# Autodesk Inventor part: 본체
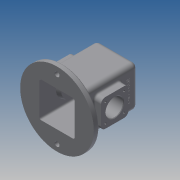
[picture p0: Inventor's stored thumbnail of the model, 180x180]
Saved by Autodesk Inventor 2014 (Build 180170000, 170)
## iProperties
Created: 2021-08
Part Number: 본체
Material: Generic
Document SubType Name: Modeling
Designer: kb542
Density: 1 g/cm^3
Appearance: Default
Author: kb542
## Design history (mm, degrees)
sketch "스케치1"
  geometry: L1 (37, 37)-(-37, 37); L2 (-37, 37)-(-37, -37); L3 (-37, -37)-(37, -37); L4 (37, -37)-(37, 37); L5 (37, 37)-(-37, -37); L6 (-37, 37)-(37, -37); 1 further point
  constraints: 12 end point, 2 midpoint, 2 parallel, 1 horizontal, 1 perpendicular
  dimensions: "d1" = 74 distance of L2.end L3.end; "d2" = 74 distance of L1.end L2.end
extrude "돌출1" new body sketch "스케치1" distance "d3" = 100; taper "d4" = 0 deg
feature "쉘1" dims "d5" = 5
sketch "스케치2"
  geometry: L1 (-32, -32)-(-32, 32) reference; L2 (-32, 32)-(32, 32) reference; L3 (32, 32)-(32, -32) reference; L4 (32, -32)-(-32, -32) reference; C1 r 67 at (0, 0); 1 further point
  constraints: 1 centre point, 1 coincident
  dimensions: "d6" = 134 diameter of C1
extrude "돌출2" join sketch "스케치2" distance "d7" = 10; taper "d8" = 0 deg
node "작업 평면1"
sketch "스케치3"
  geometry: C1 r 20 at (0, 0); 2 further points
  constraints: 2 coincident, 1 centre point
  dimensions: "d10" = 40 diameter of C1
extrude "돌출3" join sketch "스케치3" stored distance "d11" = 10; taper "d12" = 6 deg
hole "구멍1" sketch "스케치3" diameter "d13" = 21; stored, may be unused: countersink angle "d17" = 90 deg, drill point angle "d19" = 118 deg; dims "d14" = 6, "d15" = 28, "d16" = 4, "d18" = 8
sketch "스케치4"
  geometry: C1 r 67 at (0, 0) reference; A1 r 55 centre (0, 0) between (0, 55) and (0, -55)
  constraints: 2 point on circle, 2 vertical alignment, 1 centre point, 1 coincident
  dimensions: "d20" = 110 diameter of A1
hole "구멍2" sketch "스케치4" at (0, 55), (0, -55) diameter "d21" = 9; stored, may be unused: countersink angle "d25" = 90 deg, drill point angle "d27" = 118 deg; dims "d22" = 6, "d23" = 28, "d24" = 4, "d26" = 8
node "작업 평면2"
sketch "스케치5"
  geometry: L1 (12, -80)-(62, -80); L2 (62, -80)-(62, -30); L3 (62, -30)-(12, -30); L4 (12, -30)-(12, -80); L5 (12, -80)-(62, -30); L6 (62, -80)-(12, -30); L7 (-30, -110)-(104, -110) reference; L8 (20, -72)-(54, -72); L9 (54, -72)-(54, -38); L10 (54, -38)-(20, -38); L11 (20, -38)-(20, -72); L12 (20, -72)-(54, -38); L13 (54, -72)-(20, -38); C1 r 16 at (37, -55); 7 further points
  constraints: 24 end point, 7 midpoint, 4 coincident, 4 parallel, 2 horizontal, 2 perpendicular, 1 centre point, 1 point on line, 1 vertical alignment
  dimensions: "d29" = 50 distance of L2.end L3.end; "d30" = 50 distance of L1.end L2.end; "d31" = 55 distance from line of L7 point (37, -55); "d32" = 34 distance of L9.end L10.end; "d33" = 32 diameter of C1
extrude "돌출4" join sketch "스케치5" stored distance "d34" = 10; taper "d35" = 0 deg
hole "구멍3" sketch "스케치5" diameter "d36" = 3.242; stored, may be unused: countersink angle "d40" = 90 deg, drill point angle "d42" = 118 deg; dims "d37" = 8, "d38" = 28, "d39" = 4, "d41" = 10
extrude "돌출7" cut sketch "스케치5" stored distance "d48" = 10; taper "d49" = 0 deg
node "작업축1"
sketch "스케치7"
  geometry: L1 (93.8, 45)-(-93.8, 45) reference; L2 (-37, 20)-(-50, 20) reference; L3 (-50, 20)-(-50, 29) reference; L4 (-50, 29)-(-32, 29) reference; L5 (-32, 29)-(-32, -10) reference; L6 (-32, -10)-(-67, -10) reference; L7 (-67, -10)-(-67, 0) reference; L8 (-67, 0)-(-37, 0) reference; L9 (-37, 0)-(-37, 20) reference; L10 (20, 110)-(21.051, 100) reference; L11 (21.051, 100)-(37, 100) reference; L12 (37, 100)-(37, 70) reference; L13 (37, 70)-(50, 70) reference; L14 (50, 70)-(50, 61) reference; L15 (50, 61)-(32, 61) reference; L16 (32, 61)-(32, 95) reference; L17 (32, 95)-(10.5, 95) reference; L18 (10.5, 95)-(10.5, 106) reference; L19 (10.5, 106)-(14, 106) reference; L20 (14, 106)-(14, 110) reference; L21 (14, 110)-(20, 110) reference; L22 (-21.051, 100)-(-20, 110) reference; L23 (-20, 110)-(-14, 110) reference; L24 (-14, 110)-(-14, 106) reference; L25 (-14, 106)-(-10.5, 106) reference; L26 (-10.5, 106)-(-10.5, 95) reference; L27 (-10.5, 95)-(-32, 95) reference; L28 (-32, 95)-(-32, 61) reference; L29 (-32, 61)-(-50, 61) reference; L30 (-50, 61)-(-50, 70) reference; L31 (-50, 70)-(-37, 70) reference; L32 (-37, 70)-(-37, 100) reference; L33 (-37, 100)-(-21.051, 100) reference; L34 (37, 0)-(67, 0) reference; L35 (67, 0)-(67, -10) reference; L36 (67, -10)-(32, -10) reference; L37 (32, -10)-(32, 29) reference; L38 (32, 29)-(50, 29) reference; L39 (50, 29)-(50, 20) reference; L40 (50, 20)-(37, 20) reference; L41 (37, 20)-(37, 0) reference; L42 (-32, 45)-(-25, 45); L43 (-25, 45)-(-25, 22.548); L44 (-32, 20)-(-32, 45); L45 (-32, 20)-(-25, 22.548); 1 further point
  constraints: 8 end point, 1 collinear, 1 horizontal, 1 parallel, 1 perpendicular, 1 point on line
  dimensions: "d50" = 50 diameter of L44.start L1; "d51" = 7 distance between parallel lines of L44 L43; "d52" = 110 deg angle of L5 L45
revolve "회전1" sketch "스케치7" stored, may be unused: angle "d53" = 90 deg
sketch "스케치8"
  geometry: C1 r 16 at (0, 0) reference; 1 further point
extrude "돌출8" cut sketch "스케치8" stored distance "d54" = 10; taper "d55" = 0 deg
sketch "스케치9"
  geometry: L1 (0, -100)-(0, 0) reference; L2 (17, 10)-(57, 10) reference; 2 further points
  constraints: 1 other
  dimensions: "d56" = 37 distance from line of point (37, -18) L1; "d57" = 28 distance from line of point (37, -18) L2
feature "엠보싱1" sketch "스케치9" dims "d1" = 74, "d2" = 74, "d58" = 0.5, "d59" = 0
fillet "모깎기1" dims "d60" = 8
fillet "모깎기2" dims "d61" = 8
fillet "모깎기3" dims "d62" = 8
fillet "모깎기4" dims "d63" = 3
fillet "모깎기5" dims "d64" = 3
fillet "모깎기6" dims "d65" = 3
fillet "모깎기7" dims "d66" = 3
chamfer "모따기1" distance "d67" = 1; stored, may be unused: second distance "d68" = 2, angle "d69" = 45 deg
node "솔리드1"
mirror "대칭1"
mirror "대칭2"
node "절단 모서리 투영1"
other parameters: "d28" = 13
